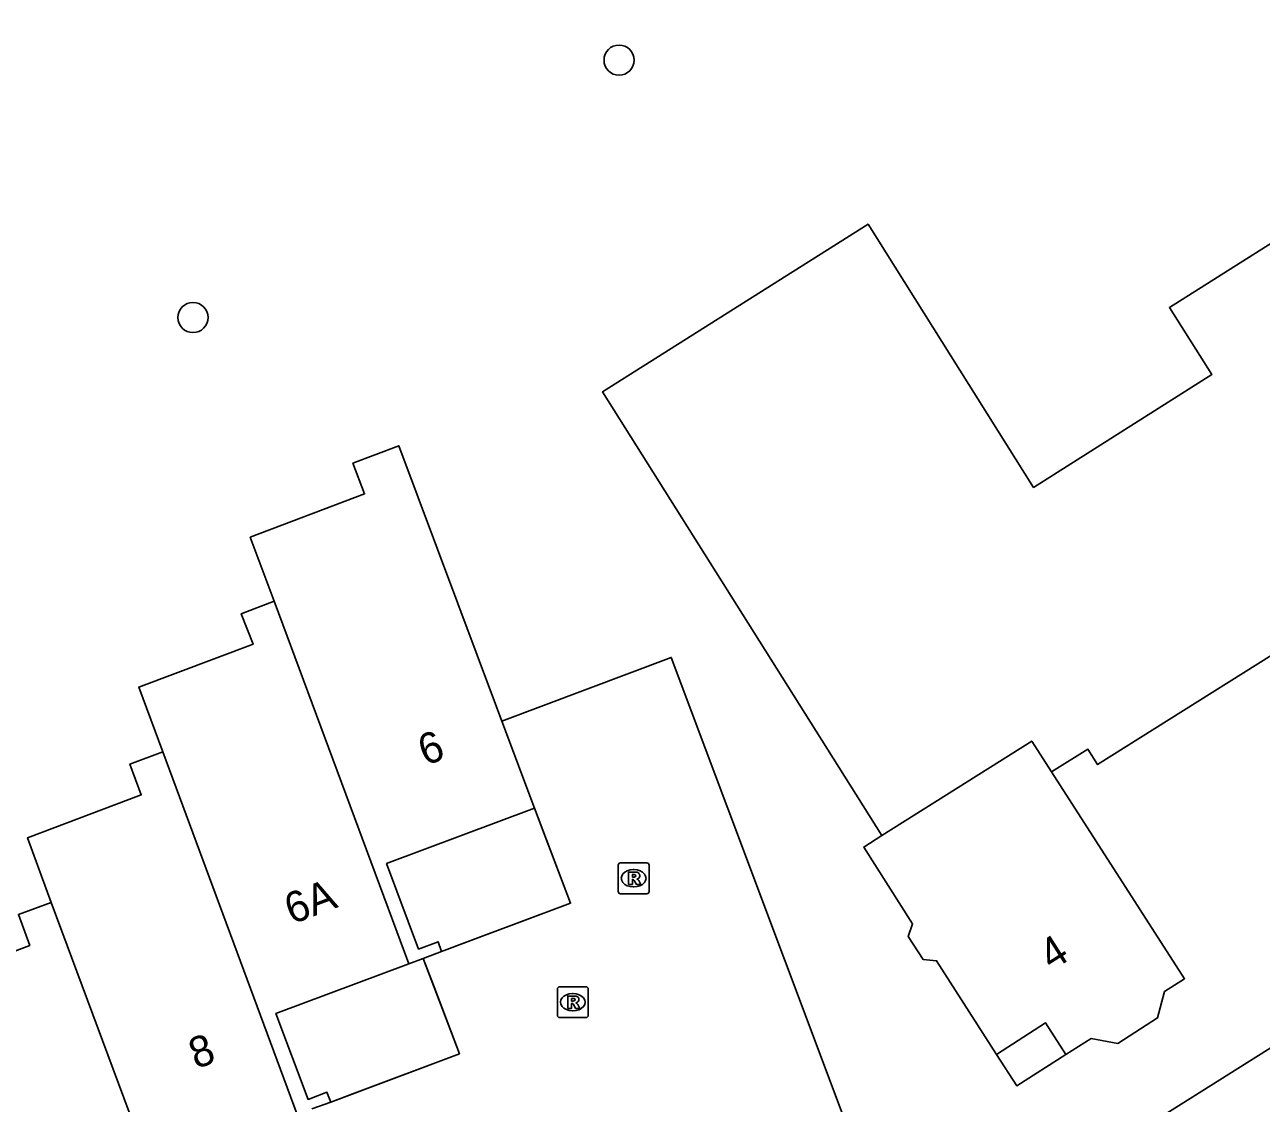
# Model space of a CAD drawing. Extents: x 160664 to 161506, y 382245 to 383288.
# Drawn here: x 160697.43 to 160737.52, y 383159.02 to 383193.99 of the extents above; entities that cross this region are included whole.
import ezdxf

# ---------------------------------------------------------------- set-up
doc = ezdxf.new("R2010")
doc.units = 0
for name, color, linetype in [('IMGEO_Boom', 7, 'Continuous'), ('IMGEO_Pand', 7, 'Continuous'), ('IMGEO_Pand_nummerreeks', 7, 'Continuous'), ('IMGEO_Pand_overbouw', 7, 'Continuous'), ('IMGEO_Rijbaan_lokaal_open', 7, 'Continuous'), ('IMGEO_Rioolput', 7, 'Continuous'), ('IMGEO_Voetpad_open', 7, 'Continuous')]:
    doc.layers.add(name, color=color, linetype=linetype)

msp = doc.modelspace()

# ---------------------------------------------------------------- linework, layer by layer
at = {"layer": 'IMGEO_Boom'}
for centre in [(160716.701, 383192.839), (160702.886, 383184.494)]:
    msp.add_circle(centre, 0.489, dxfattribs=at)
at = {"layer": 'IMGEO_Pand'}
for points in [[(160787.928, 383196.514), (160781.611, 383192.511), (160780.931, 383193.584), (160769.454, 383186.323), (160770.111, 383185.284), (160767.179, 383183.428), (160766.591, 383184.358), (160764.181, 383182.859), (160764.777, 383181.934), (160761.869, 383180.063), (160761.204, 383181.097), (160749.748, 383173.844), (160750.432, 383172.762), (160744.104, 383168.763), (160740.194, 383175.013), (160732.213, 383169.997), (160731.898, 383170.498), (160730.725, 383169.759)], [(160725.222, 383167.694), (160724.191, 383169.333), (160716.168, 383182.089), (160724.771, 383187.521), (160730.139, 383178.986), (160735.914, 383182.644), (160734.541, 383184.817), (160742.738, 383189.996), (160743.515, 383188.774), (160746.247, 383190.523), (160749.352, 383185.672), (160753.714, 383188.406), (160750.443, 383193.636), (160752.509, 383194.944)], [(160705.515, 383175.3), (160704.744, 383177.37), (160708.449, 383178.777), (160708.071, 383179.767), (160709.56, 383180.338), (160712.727, 383171.875), (160712.903, 383171.405)], [(160701.907, 383170.408), (160701.128, 383172.509), (160704.833, 383173.901), (160704.452, 383174.89), (160705.515, 383175.3)], [(160705.515, 383175.3), (160709.88, 383163.538)], [(160713.959, 383168.584), (160712.903, 383171.405)], [(160730.725, 383169.759), (160730.082, 383170.759), (160725.222, 383167.694)], [(160698.292, 383165.532), (160697.521, 383167.622), (160701.207, 383169.02), (160700.84, 383170.015), (160701.907, 383170.408)], [(160706.268, 383158.657), (160701.907, 383170.408)], [(160730.725, 383169.759), (160735.037, 383163.056), (160734.385, 383162.64), (160734.158, 383161.783), (160732.874, 383160.954), (160732.004, 383161.117), (160731.185, 383160.597), (160730.527, 383161.622), (160728.942, 383160.603), (160726.993, 383163.638), (160726.559, 383163.68), (160726.078, 383164.425), (160726.216, 383164.838), (160724.635, 383167.324), (160725.222, 383167.694)], [(160710.948, 383163.942), (160710.838, 383164.256), (160710.202, 383164.017), (160709.164, 383166.789), (160713.959, 383168.584)], [(160694.67, 383160.647), (160693.89, 383162.739), (160697.593, 383164.138), (160697.226, 383165.143), (160698.292, 383165.532)], [(160702.652, 383153.785), (160698.292, 383165.532)], [(160710.348, 383163.713), (160710.948, 383163.942)], [(160707.355, 383159.055), (160707.23, 383159.374), (160706.616, 383159.143), (160705.574, 383161.925), (160709.88, 383163.538)], [(160709.88, 383163.538), (160710.348, 383163.713)], [(160706.744, 383158.835), (160707.355, 383159.055)]]:
    msp.add_lwpolyline(points, dxfattribs=at)
at = {"layer": 'IMGEO_Pand_overbouw'}
for points in [[(160713.959, 383168.584), (160709.164, 383166.789), (160710.202, 383164.017), (160710.838, 383164.256), (160710.948, 383163.942), (160715.129, 383165.5)], [(160710.348, 383163.713), (160709.88, 383163.538), (160705.574, 383161.925), (160706.616, 383159.143), (160707.23, 383159.374), (160707.355, 383159.055), (160711.525, 383160.624)], [(160730.527, 383161.622), (160728.942, 383160.603), (160729.595, 383159.587), (160731.185, 383160.597)]]:
    msp.add_lwpolyline(points, close=True, dxfattribs=at)
at = {"layer": 'IMGEO_Rijbaan_lokaal_open'}
for points in [[(160712.903, 383171.405), (160718.393, 383173.471), (160725.736, 383153.883), (160725.98, 383153.338)], [(160713.959, 383168.584), (160714.272, 383167.758), (160715.129, 383165.5), (160711.685, 383164.217), (160710.948, 383163.942)], [(160710.348, 383163.713), (160710.68, 383162.842), (160711.525, 383160.624), (160708.124, 383159.344), (160707.355, 383159.055)]]:
    msp.add_lwpolyline(points, dxfattribs=at)
at = {"layer": 'IMGEO_Rioolput'}
for p, q in [((160716.673, 383165.886), (160716.673, 383166.738)), ((160716.748, 383166.812), (160717.6, 383166.812)), ((160717.674, 383166.738), (160717.674, 383165.886)), ((160717.161, 383166.592), (160717.186, 383166.592)), ((160717.6, 383165.812), (160716.748, 383165.812)), ((160717.184, 383166.032), (160717.159, 383166.032)), ((160714.699, 383161.869), (160714.699, 383162.721)), ((160714.774, 383162.795), (160715.626, 383162.795)), ((160715.7, 383162.721), (160715.7, 383161.869)), ((160715.187, 383162.575), (160715.212, 383162.575)), ((160715.626, 383161.795), (160714.774, 383161.795)), ((160715.21, 383162.015), (160715.185, 383162.015))]:
    msp.add_line(p, q, dxfattribs=at)
for points in [[(160716.673, 383165.886), (160716.673, 383166.738)], [(160716.748, 383166.812), (160717.6, 383166.812)], [(160717.674, 383166.738), (160717.674, 383165.886)], [(160717.262, 383166.51), (160717.01, 383166.512), (160717.01, 383166.112)], [(160717.01, 383166.112), (160717.134, 383166.112), (160717.134, 383166.274), (160717.145, 383166.274)], [(160717.188, 383166.431), (160717.134, 383166.431), (160717.134, 383166.35)], [(160717.134, 383166.35), (160717.186, 383166.35)], [(160717.192, 383166.245), (160717.263, 383166.112), (160717.403, 383166.112), (160717.338, 383166.238)], [(160717.6, 383165.812), (160716.748, 383165.812)], [(160714.699, 383161.869), (160714.699, 383162.721)], [(160714.774, 383162.795), (160715.626, 383162.795)], [(160715.7, 383162.721), (160715.7, 383161.869)], [(160715.288, 383162.493), (160715.036, 383162.495), (160715.036, 383162.095)], [(160715.036, 383162.095), (160715.16, 383162.095), (160715.16, 383162.257), (160715.171, 383162.257)], [(160715.214, 383162.414), (160715.16, 383162.414), (160715.16, 383162.333)], [(160715.16, 383162.333), (160715.212, 383162.333)], [(160715.218, 383162.228), (160715.289, 383162.095), (160715.429, 383162.095), (160715.364, 383162.221)], [(160715.626, 383161.795), (160714.774, 383161.795)]]:
    msp.add_lwpolyline(points, dxfattribs=at)
for centre, radius, start, end in [((160716.75, 383166.736), 0.0765, 91.552, 178.448), ((160716.75, 383166.736), 0.0765, 91.552, 178.448), ((160717.598, 383166.736), 0.0765, 1.552, 88.448), ((160717.598, 383166.736), 0.0765, 1.552, 88.448), ((160717.144, 383166.221), 0.0533, 26.0293, 88.6989), ((160717.17, 383166.539), 0.19, 274.7715, 282.9687), ((160717.194, 383166.335), 0.0964, 77.0061, 93.1865), ((160717.208, 383166.392), 0.0378, 276.6634, 79.6772), ((160717.261, 383166.4), 0.109, 350.3612, 89.416), ((160717.259, 383166.4), 0.112, 277.5842, 350.9817), ((160717.243, 383166.185), 0.108, 29.5134, 73.7905), ((160716.75, 383165.888), 0.0765, 181.552, 268.448), ((160716.75, 383165.888), 0.0765, 181.552, 268.448), ((160717.598, 383165.888), 0.0765, 271.552, 358.448), ((160717.598, 383165.888), 0.0765, 271.552, 358.448), ((160714.776, 383162.719), 0.0765, 91.552, 178.448), ((160714.776, 383162.719), 0.0765, 91.552, 178.448), ((160715.624, 383162.719), 0.0765, 1.552, 88.448), ((160715.624, 383162.719), 0.0765, 1.552, 88.448), ((160715.17, 383162.204), 0.0533, 26.0293, 88.6989), ((160715.196, 383162.522), 0.19, 274.7715, 282.9687), ((160715.22, 383162.318), 0.0964, 77.0061, 93.1865), ((160715.234, 383162.375), 0.0378, 276.6634, 79.6772), ((160715.287, 383162.383), 0.109, 350.3612, 89.416), ((160715.285, 383162.383), 0.112, 277.5842, 350.9817), ((160715.269, 383162.168), 0.108, 29.5134, 73.7905), ((160714.776, 383161.871), 0.0765, 181.552, 268.448), ((160714.776, 383161.871), 0.0765, 181.552, 268.448), ((160715.624, 383161.871), 0.0765, 271.552, 358.448), ((160715.624, 383161.871), 0.0765, 271.552, 358.448)]:
    msp.add_arc(centre, radius, start, end, dxfattribs=at)
for centre, major_axis, ratio, start_param, end_param in [((160717.16, 383166.312), (-0.387, 0.002), 0.722429, 4.712389, 7.853982), ((160717.185, 383166.312), (-0.39, 0.002), 0.717154, 1.570796, 4.712389), ((160715.186, 383162.295), (-0.387, 0.002), 0.722429, 4.712389, 7.853982), ((160715.211, 383162.295), (-0.39, 0.002), 0.717154, 1.570796, 4.712389)]:
    msp.add_ellipse(centre, major_axis=major_axis, ratio=ratio, start_param=start_param, end_param=end_param, dxfattribs=at)
at = {"layer": 'IMGEO_Voetpad_open'}
msp.add_lwpolyline([(160730.374, 383156.128), (160757.849, 383173.421), (160766.092, 383178.668), (160766.151, 383178.573), (160766.522, 383178.802), (160769.404, 383180.67), (160769.35, 383180.762), (160772.211, 383182.539), (160787.728, 383192.359)], dxfattribs=at)

# ---------------------------------------------------------------- texts
at = {"layer": 'IMGEO_Pand_nummerreeks'}
for s, rotation, p in [('6', 20.5233, (160710.42, 383169.95)), ('6A', 20.542, (160706.091, 383164.809)), ('4', 32.5154, (160730.73, 383163.298)), ('8', 20.3161, (160702.985, 383160.116))]:
    msp.add_text(s, height=1, rotation=rotation, dxfattribs=at).set_placement(p)

doc.saveas('drawing.dxf')
